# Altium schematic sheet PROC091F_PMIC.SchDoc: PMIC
size 431 x 279 mm; Date: Not shown in title block; ApprovedBy: Not shown in title block; CheckedBy: Not shown in title block; Author: Not shown in title block; CompanyName: Not shown in title block; DrawnBy: Antony/Bala; Engineer: Not shown in title block; Organization: Not shown in title block; Address1: Not shown in title block; Address2: Not shown in title block; Address3: Not shown in title block; Address4: Not shown in title block; DocumentNumber: 5; Revision: Use project parameter SCH_Rev; SheetNumber: 5; SheetTotal: 12; PageSetup: Record=PageOptions¦CenterHorizontal=True¦CenterVertical=True¦PrintScale=1.00¦XCorrection=1.00¦YCorrection=1.00¦PrintKind=0¦BorderSize=5000000¦LeftOffset=0¦BottomOffset=0¦Orientation=2¦PaperLength=1000¦PaperWidth=1000¦Scale=100¦PaperSource=15¦PrintQuality=600¦MediaType=1¦DitherType=10¦PaperKind=Letter¦PrintScaleMode=1
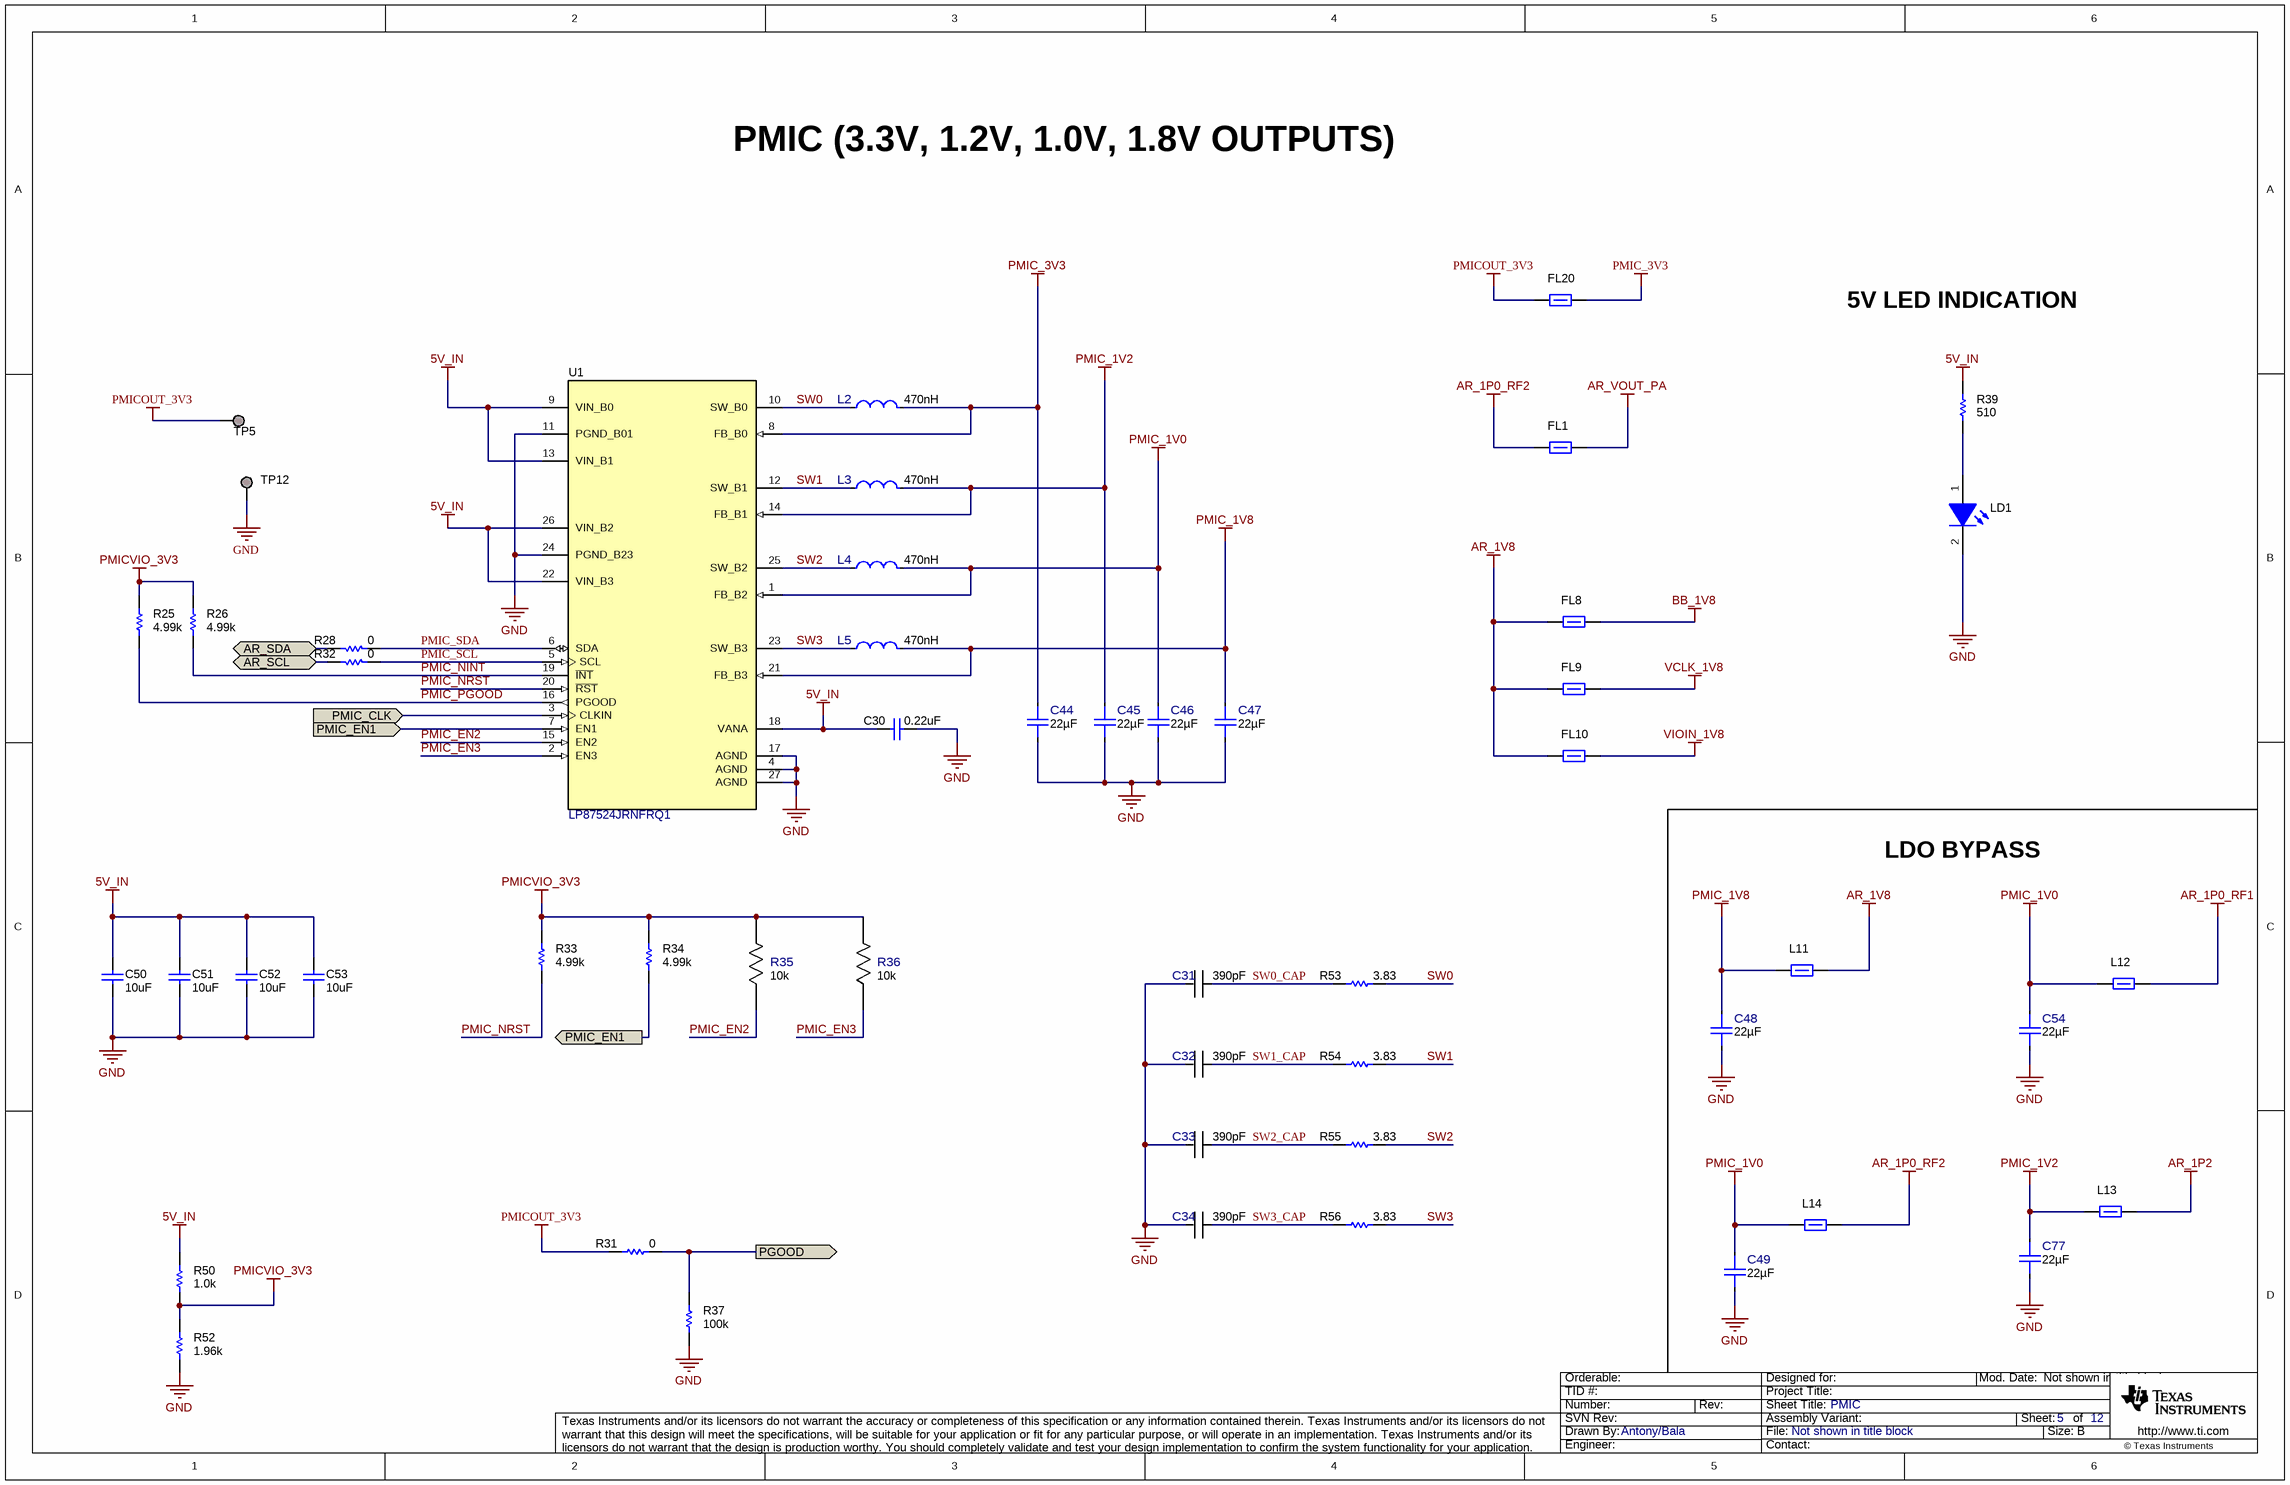
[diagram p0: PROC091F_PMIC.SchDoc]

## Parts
C30  value 0.22uF  [0201_033L]  (hidden comment: LMK063BJ224MP-F)
C31  Cap_F: 390pF  [FP-TMK063CG391JT-F_0201 (0603 Metric)-IPC_C]  (hidden comment: TMK063CG391JT-F)
C32  Cap_F: 390pF  [FP-TMK063CG391JT-F_0201 (0603 Metric)-IPC_C]  (hidden comment: TMK063CG391JT-F)
C33  Cap_F: 390pF  [FP-TMK063CG391JT-F_0201 (0603 Metric)-IPC_C]  (hidden comment: TMK063CG391JT-F)
C34  Cap_F: 390pF  [FP-TMK063CG391JT-F_0201 (0603 Metric)-IPC_C]  (hidden comment: TMK063CG391JT-F)
C44  Cap_F: 22µF  [FP-CL05A226MQ5N6J8_0402-IPC_C]  (hidden comment: CL05A226MQ5N6J8)
C45  Cap_F: 22µF  [FP-CL05A226MQ5N6J8_0402-IPC_C]  (hidden comment: CL05A226MQ5N6J8)
C46  Cap_F: 22µF  [FP-CL05A226MQ5N6J8_0402-IPC_C]  (hidden comment: CL05A226MQ5N6J8)
C47  Cap_F: 22µF  [FP-CL05A226MQ5N6J8_0402-IPC_C]  (hidden comment: CL05A226MQ5N6J8)
C48  Cap_F: 22µF  [FP-CL05A226MQ5N6J8_0402-IPC_C]  (hidden comment: CL05A226MQ5N6J8)
C49  Cap_F: 22µF  [FP-CL05A226MQ5N6J8_0402-IPC_C]  (hidden comment: CL05A226MQ5N6J8)
C50  value 10uF  [0402_070]  (hidden comment: CL05A106MP5NUNC)
C51  value 10uF  [0402_070]  (hidden comment: CL05A106MP5NUNC)
C52  value 10uF  [0402_070]  (hidden comment: CL05A106MP5NUNC)
C53  value 10uF  [0402_070]  (hidden comment: CL05A106MP5NUNC)
C54  Cap_F: 22µF  [FP-CL05A226MQ5N6J8_0402-IPC_C]  (hidden comment: CL05A226MQ5N6J8)
C77  Cap_F: 22µF  [FP-CL05A226MQ5N6J8_0402-IPC_C]  (hidden comment: CL05A226MQ5N6J8)
FL1  BLM15PD300SZ1D  [0402L]  (value not drawn)
FL8  BLM15PD300SZ1D  [0402L]  (value not drawn)
FL9  BLM15PD300SZ1D  [0402L]  (value not drawn)
FL10  BLM15PD300SZ1D  [0402L]  (value not drawn)
FL20  BLM15PD300SZ1D  [0402L]  (value not drawn)
L2  Ind_H: 470nH  [FP-MCKK2012TR47M_0805 (2012 Metric)-IPC_C]  (hidden comment: MCKK2012TR47M)
L3  Ind_H: 470nH  [FP-MCKK2012TR47M_0805 (2012 Metric)-IPC_C]  (hidden comment: MCKK2012TR47M)
L4  Ind_H: 470nH  [FP-MCKK2012TR47M_0805 (2012 Metric)-IPC_C]  (hidden comment: MCKK2012TR47M)
L5  Ind_H: 470nH  [FP-MCKK2012TR47M_0805 (2012 Metric)-IPC_C]  (hidden comment: MCKK2012TR47M)
L11  BLM18SG260TN1D  [0603L]  (value not drawn)
L12  BLM18SG260TN1D  [0603L]  (value not drawn)
L13  BLM18SG260TN1D  [0603L]  (value not drawn)
L14  BLM18SG260TN1D  [0603L]  (value not drawn)
LD1  APHHS1005CGCK  [APHHS1005_Green]  (value not drawn)
R25  value 4.99k  [0201L]  (hidden comment: RC0201FR-074K99L)
R26  value 4.99k  [0201L]  (hidden comment: RC0201FR-074K99L)
R28  Res_ohm: 0  [FP-RC0201JR-070RL_0201 (0603 Metric)-MFG]  (hidden comment: RC0201JR-070RL)
R31  Res_ohm: 0  [FP-RC0201JR-070RL_0201 (0603 Metric)-MFG]  (hidden comment: RC0201JR-070RL)
R32  Res_ohm: 0  [FP-RC0201JR-070RL_0201 (0603 Metric)-MFG]  (hidden comment: RC0201JR-070RL)
R33  value 4.99k  [0201L]  (hidden comment: RC0201FR-074K99L)
R34  value 4.99k  [0201L]  (hidden comment: RC0201FR-074K99L)
R35  Res_ohm: 10k  [FP-RR0306P-103-D_0201-IPC_C]  (hidden comment: RR0306P-103-D)
R36  Res_ohm: 10k  [FP-RR0306P-103-D_0201-IPC_C]  (hidden comment: RR0306P-103-D)
R37  value 100k  [0201L]  (hidden comment: CRCW0201100KFKED)
R39  value 510  [0201L]  (hidden comment: RC0201JR-07510RL)
R50  value 1.0k  [0201L]  (hidden comment: RC0201JR-071KL)
R52  value 1.96k  [0201L]  (hidden comment: RC0201FR-071K96L)
R53  Res_ohm: 3.83  [FP-RC0402FR-073R83L_0402 (1005 Metric)-IPC_C]  (hidden comment: RC0402FR-073R83L)
R54  Res_ohm: 3.83  [FP-RC0402FR-073R83L_0402 (1005 Metric)-IPC_C]  (hidden comment: RC0402FR-073R83L)
R55  Res_ohm: 3.83  [FP-RC0402FR-073R83L_0402 (1005 Metric)-IPC_C]  (hidden comment: RC0402FR-073R83L)
R56  Res_ohm: 3.83  [FP-RC0402FR-073R83L_0402 (1005 Metric)-IPC_C]  (hidden comment: RC0402FR-073R83L)
TP5  TESTPOINT  [TP_25MIL-SMT]  (value not drawn)  (no BOM)
TP12  TESTPOINT  [TP_VIA_060RND040]  (value not drawn)  (no BOM)
U1  LP87524JRNFRQ1  [RNF0026C]

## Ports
AR_SCL (bidir), AR_SDA (bidir), PGOOD (out), PMIC_CLK (in), PMIC_EN1 (in), PMIC_EN1 (out)

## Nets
5V_IN: C30.1 C50.1 C51.1 C52.1 C53.1 R39.1 R50.2 U1.9(VIN_B0) U1.13(VIN_B1) U1.18(VANA) U1.22(VIN_B3) U1.26(VIN_B2)
AR_1P0_RF1: L12.2
AR_1P0_RF2: FL1.1 L14.2
AR_1P2: L13.2
AR_1V8: FL8.1 FL9.1 FL10.1 L11.2
AR_VOUT_PA: FL1.2
BB_1V8: FL8.2
GND: C30.2 C31.2 C32.2 C33.2 C34.2 C44.2 C45.2 C46.2 C47.2 C48.2 C49.2 C50.2 C51.2 C52.2 C53.2 C54.2 C77.2 LD1.2(K) R37.1 R52.1 TP12.1 U1.4(AGND) U1.11(PGND_B01) U1.17(AGND) U1.24(PGND_B23) U1.27(AGND)
PMIC_1V0: C46.1 C49.1 C54.1 L4.1 L12.1 L14.1 U1.1(FB_B2)
PMIC_1V2: C45.1 C77.1 L3.1 L13.1 U1.14(FB_B1)
PMIC_1V8: C47.1 C48.1 L5.1 L11.1 U1.21(FB_B3)
PMIC_3V3: C44.1 FL20.2 L2.1 U1.8(FB_B0)
PMICOUT_3V3: FL20.1 R31.2 TP5.1
PMICVIO_3V3: R25.2 R26.2 R33.2 R34.2 R35.2 R36.2 R50.1 R52.2
VCLK_1V8: FL9.2
VIOIN_1V8: FL10.2
AR_SCL: R32.1 ; port AR_SCL
AR_SDA: R28.1 ; port AR_SDA
PGOOD: R31.1 R37.2 ; port PGOOD
PMIC_CLK: U1.3(CLKIN) ; port PMIC_CLK
PMIC_EN1: R34.1 U1.7(EN1) ; port PMIC_EN1
PMIC_EN2: R35.1 U1.15(EN2)
PMIC_EN3: R36.1 U1.2(EN3)
PMIC_NINT: R26.1 U1.19(~{INT})
PMIC_NRST: R33.1 U1.20(~{RST})
PMIC_PGOOD: R25.1 U1.16(PGOOD)
PMIC_SCL: R32.2 U1.5(SCL)
PMIC_SDA: R28.2 U1.6(SDA)
SW0: L2.2 R53.2 U1.10(SW_B0)
SW0_CAP: C31.1 R53.1
SW1: L3.2 R54.2 U1.12(SW_B1)
SW1_CAP: C32.1 R54.1
SW2: L4.2 R55.2 U1.25(SW_B2)
SW2_CAP: C33.1 R55.1
SW3: L5.2 R56.2 U1.23(SW_B3)
SW3_CAP: C34.1 R56.1
NetLD1_1: LD1.1(A) R39.2

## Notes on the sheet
- PMIC (3.3V, 1.2V, 1.0V, 1.8V OUTPUTS)
- 5V LED INDICATION
- LDO BYPASS

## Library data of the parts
C30 = CMP-0009781-1: CAP, CERM, 0.22 uF, 10 V, +/- 20%, X5R, 0201; Manufacturer: Taiyo Yuden; AEC Category: Q200; AEC Qualified: N; Cap_Case: 0201; Cap_F: 220nF; SizeArea_mm2: 0.18; SizeAreaWB_mm2: 2.08; SizeX_mm: 0.6; SizeY_mm: 0.3; SizeZ_mm: 0.33; TaMax_C: 85°C; TaMin_C: -55°C; U/M: EA; Value1: Unknown; Value2: 10V
C31-C34 = CMP-0086438-1: CAP CER 390PF 25V C0G/NP0 0201; Manufacturer: Taiyo Yuden; AEC Qualified: No; SizeZ_mm: 0.33mm; Symbol Name: SYM-TMK063CG391JT-F; TempCo: 30ppm/°C; Tolerance_%: 5%
C44-C47 = CMP-0089043-3: CAP CER 22UF 6.3V X5R 0402; Manufacturer: Samsung Electro-Mechanics; AEC Qualified: No; SizeZ_mm: 0.55mm; TempCo: 15%; Tolerance_%: 20%
C48 C49 C54 C77 = CMP-0089043-3: CAP CER 22UF 6.3V X5R 0402; Manufacturer: Samsung Electro-Mechanics; TempCo: 15%; AEC Qualified: No; Tolerance_%: 20%; SizeZ_mm: 0.55mm
C50-C53 = CMP-0006339-4: CAP, CERM, 10 uF, 10 V, +/- 20%, X5R, 0402; Manufacturer: Samsung Electro-Mechanics; AEC Category: Q200; AEC Qualified: N; Cap_Case: 0402; Cap_F: 10µF; SizeArea_mm2: 0.5; SizeAreaWB_mm2: 3; SizeX_mm: 1; SizeZ_mm: 0.6; TaMax_C: 85°C; TaMin_C: -55°C; U/M: EA; Value1: Unknown; Value2: 10V
FL1 FL8-FL10 FL20 = CMP-0078934-1: Inductor, Ferrite Bead, Ferrite, 2.2 A, 0.035 ohm, AEC-Q200 Grade 1, SMD; Manufacturer: MuRata; AEC Category: Q200; AEC Grade: 1; AEC Qualified: Y; DCR_ohm: 0.035; Imax_A: 2.2A; SizeArea_mm2: 0.5; SizeAreaWB_mm2: 3; SizeZ_mm: 0.6
L2-L5 = CMP-0087178-1: FIXED IND 470NH 4.5A 39 MOHM SMD; Manufacturer: Taiyo Yuden; AEC Qualified: No; DCR_ohm: 0.032; Irms: 3.1A; Material: Metal; SizeZ_mm: 1mm; Symbol Name: SYM-MCKK2012TR47M
L11-L14 = CMP-0003354-2: Ferrite Bead, 26 ohm @ 100 MHz, 6 A, 0603; Manufacturer: MuRata; ZTyp@100MHz_Ohm: 26; SizeAreaWB_mm2: 4.68; DCR_ohm: 7m; Value1: 0.007 ohm; Value: 26 ohm; Imax_A: 6A; SizeZ_mm: 1; SizeX_mm: 1.6; SizeY_mm: 0.8; SizeArea_mm2: 1.28
LD1 = CMP-0067682-2: LED, Green, SMD; Manufacturer: Kingbright; Angle: 120.0; Power_TotalModule: 75mW; SizeZ_mm: 0.6; Vf_V: 2.1V; Vr_V: 5V; Io_A: 20mA; Ir_A: 10µA; SizeArea_mm2: 0.5; SizeAreaWB_mm2: 3.0; SizeX_mm: 1.0; Tjmax_C: 85°C; Value1: 0.075W
R25 R26 R33 R34 = CMP-0027745-1: RES, 4.99 k, 1%, 0.05 W, 0201; Manufacturer: Yageo America; AEC Category: Q200; AEC Qualified: N; EIA_Code: E96; Power_W: 50mW; SizeArea_mm2: 0.18; SizeX_mm: 0.6; SizeY_mm: 0.3; SizeZ_mm: 0.26; TempCo: 200 ppm/C; U/M: EA; Value2: 0.05W; Value_Code: 4k99; VDC_V: 25V
R28 R31 R32 = CMP-0086442-2: RES SMD 0 OHM JUMPER 1/20W 0201; Manufacturer: Yageo; AEC Qualified: No; Power_W: 50mW; SizeZ_mm: 0.26mm; TempCo: 200ppm/°C; Tolerance_%: 5%; VDC_V: 25V
R35 R36 = CMP-0088002-1: 10 kOhms ±0.5% 0.05W, 1/20W Chip Resistor 0201 (0603 Metric)  Thin Film; Manufacturer: Susumu; AEC Qualified: No; Power_W: 50mW; SizeZ_mm: 0.26mm; Symbol Name: SYM-RR0306P-103-D; TempCo: 25ppm/°C; VDC_V: 15V
R37 = CMP-0027261-3: RES, 100 k, 1%, 0.05 W, 0201; Manufacturer: Vishay-Dale; AEC Category: Q200; AEC Qualified: N; EIA_Code: E96; Power_W: 50mW; SizeArea_mm2: 0.18; SizeX_mm: 0.6; SizeY_mm: 0.3; SizeZ_mm: 0.26; TempCo: 100 ppm/C; Value2: 0.05W; VDC_V: 30V
R39 = CMP-0027137-1: RES, 510, 5%, 0.05 W, 0201; Manufacturer: Yageo America; AEC Category: Q200; AEC Qualified: N; EIA_Code: E24; Power_W: 50mW; SizeArea_mm2: 0.18; SizeX_mm: 0.6; SizeY_mm: 0.3; SizeZ_mm: 0.26; TempCo: 200 ppm/C; U/M: EA; Value2: 0.05W; Value_Code: 510R; VDC_V: 25V
R50 = CMP-0027052-1: RES, 1.0 k, 5%, 0.05 W, 0201; Manufacturer: Yageo America; AEC Category: Q200; AEC Qualified: N; EIA_Code: E24; Power_W: 50mW; Res_ohm: 1k; SizeArea_mm2: 0.18; SizeX_mm: 0.6; SizeY_mm: 0.3; SizeZ_mm: 0.26; TempCo: 200 ppm/C; U/M: EA; Value2: 0.05W; Value_Code: 1k00; VDC_V: 25V
R52 = CMP-0027452-1: RES, 1.96 k, 1%, 0.05 W, 0201; Manufacturer: Yageo America; AEC Category: Q200; AEC Qualified: N; EIA_Code: E96; Power_W: 50mW; SizeArea_mm2: 0.18; SizeX_mm: 0.6; SizeY_mm: 0.3; SizeZ_mm: 0.26; TempCo: 200 ppm/C; U/M: EA; Value2: 0.05W; Value_Code: 1k96; VDC_V: 25V
R53-R56 = CMP-0086444-2: RES Thick Film SMD 3.83Ω 1% 1/16W 0402 200ppm/°C; Manufacturer: Yageo; AEC Qualified: No; Power_W: 63mW; VDC_V: 50V; SizeZ_mm: 0.4mm
TP5 TP12 = CMP-0078143-3: TEST POINT.  No entry in BOM.
U1 = CMP-0079120-2: 4-A + 2.5-A + Two 1.5-A Buck Converters With Integrated Switches, RNF0026C (VQFN-HR-26); Alternate PartNumber: LP87524JRNFTQ1; Alternate Manufacturer: Texas Instruments; SizeAreaWB_mm2: 27.5; SizeZ_mm: 0.9; SizeX_mm: 4; SizeY_mm: 4.5; SizeArea_mm2: 18; CompType: IC; AEC Qualified: Y; AEC Category: Q200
